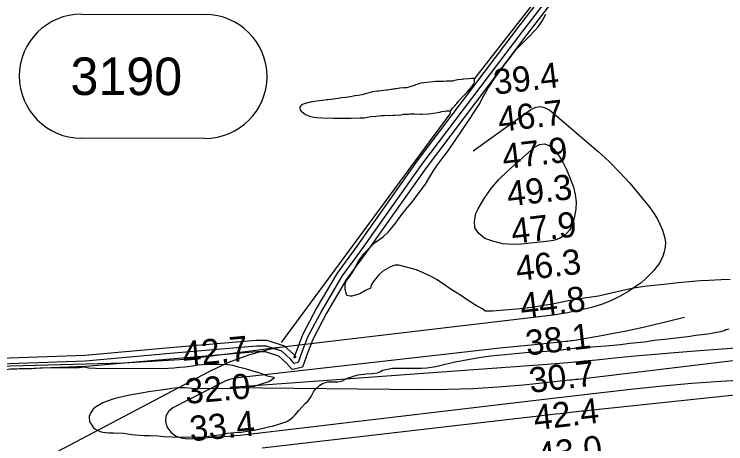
# Model space of a CAD drawing. Extents: x 3192986 to 3230865, y 867483 to 892886.
# Drawn here: x 3199829 to 3201724, y 880658 to 881802 of the extents above; entities that cross this region are included whole.
import ezdxf

# ---------------------------------------------------------------- set-up
doc = ezdxf.new("R2010")
doc.units = 0
for name, color, linetype in [('V-RIVR-RANG', 7, 'Continuous'), ('V-ROAD-CNTR', 7, 'Continuous'), ('V-ROAD-IDEN', 7, 'Continuous'), ('V-SITE-VEGE', 7, 'Continuous'), ('V-TOPO-MAJR', 7, 'Continuous'), ('V-TOPO-MINR', 7, 'Continuous'), ('V-TOPO-SHOR', 7, 'Continuous')]:
    doc.layers.add(name, color=color, linetype=linetype)

msp = doc.modelspace()

# ---------------------------------------------------------------- linework, layer by layer
at = {"layer": 'V-ROAD-CNTR'}
for points in [[(3201448.8, 882103.3), (3201182.4, 881757.5), (3200913.6, 881402.3), (3200753.9, 881176.2), (3200701.4, 881104.7), (3200647.8, 881013.7), (3200610.1, 880942), (3200596, 880905.2), (3200584.9, 880875), (3200574.7, 880872.6), (3200564.6, 880883.9), (3200541.1, 880905.2), (3200500, 880918.5), (3200474.1, 880918.4), (3200244, 880899.1), (3200018.3, 880878.8), (3199764.7, 880869.4)], [(3201402.2, 882067.4), (3201170.5, 881766.6), (3200901.5, 881411.1), (3200741.7, 881184.9), (3200688.8, 881113), (3200634.7, 881021), (3200596.4, 880948.2), (3200582, 880910.5), (3200573.6, 880887.7), (3200579.9, 880889.2), (3200575.3, 880894.5), (3200572.6, 880896.9)], [(3201427.8, 882051.6), (3201194.4, 881748.4), (3200925.7, 881393.4), (3200766, 881167.4), (3200713.9, 881096.5), (3200660.9, 881006.4), (3200623.8, 880935.8), (3200610.1, 880900), (3200596.3, 880862.2), (3200577.8, 880857.9)], [(3200572.6, 880896.9), (3200548.8, 880918.5), (3200502.3, 880933.5), (3200473.4, 880933.4), (3200242.7, 880914), (3200017.4, 880893.8), (3199764.3, 880884.3), (3199588.6, 880880.7), (3199430.3, 880873.1), (3199300.5, 880864.7), (3199227.2, 880871.2), (3199143.4, 880885.6), (3199093.7, 880891.8), (3199041.7, 880895.9), (3199014.5, 880901.6), (3199011.6, 880904.6)], [(3200577.8, 880857.9), (3200569.4, 880855.9), (3200553.9, 880873.3), (3200533.5, 880891.9), (3200497.7, 880903.5), (3200474.7, 880903.4), (3200245.3, 880884.1), (3200019.3, 880863.9), (3199765.2, 880854.4), (3199589.6, 880850.7), (3199432, 880843.2), (3199300.1, 880834.6), (3199223.3, 880841.4), (3199139, 880856), (3199090.7, 880861.9), (3199037.4, 880866.1), (3199003.9, 880873.2)]]:
    msp.add_lwpolyline(points, dxfattribs=at)
at = {"layer": 'V-ROAD-IDEN'}
for p, q in [((3200007.4, 881802.3), (3200337.4, 881801.7)), ((3200007.4, 881802.3), (3200007.4, 881802.3)), ((3200007.4, 881802.3), (3200337.4, 881801.7)), ((3200336.7, 881471.7), (3200006.7, 881472.3)), ((3200336.7, 881471.7), (3200006.7, 881472.3))]:
    msp.add_line(p, q, dxfattribs=at)
for centre, start, end in [((3200007, 881637.3), 89.8917, 269.8917), ((3200007, 881637.3), 89.8917, 269.8917), ((3200337, 881636.7), 269.8917, 89.8917), ((3200337, 881636.7), 269.8917, 89.8917)]:
    msp.add_arc(centre, 165, start, end, dxfattribs=at)
at = {"layer": 'V-SITE-VEGE'}
for p, q in [((3201235.5, 881785.4), (3201245, 881802.3)), ((3201225.1, 881769.4), (3201235.5, 881785.4)), ((3201202.4, 881745), (3201225.1, 881769.4)), ((3201166.4, 881709.4), (3201202.4, 881745)), ((3201157, 881697.1), (3201166.4, 881709.4)), ((3201144.7, 881680.2), (3201157, 881697.1)), ((3201118.1, 881644.5), (3201134.2, 881667.1)), ((3201134.2, 881667.1), (3201144.7, 881680.2)), ((3201096.4, 881613.5), (3201107.7, 881631.4)), ((3201107.7, 881631.4), (3201118.1, 881644.5)), ((3201089.7, 881604.1), (3201096.4, 881613.5)), ((3201076.4, 881579.7), (3201085.9, 881595.7)), ((3201085.9, 881595.7), (3201089.7, 881604.1)), ((3201068.8, 881564.6), (3201076.4, 881579.7)), ((3201050.8, 881538.3), (3201068.8, 881564.6)), ((3201046.1, 881528.9), (3201050.8, 881538.3)), ((3201021.5, 881493.2), (3201046.1, 881528.9)), ((3201005.4, 881468.8), (3201021.5, 881493.2)), ((3200984.5, 881438.7), (3201005.4, 881468.8)), ((3200972.2, 881422.7), (3200984.5, 881438.7)), ((3200956.1, 881401.1), (3200972.2, 881422.7)), ((3200946.6, 881387), (3200956.1, 881401.1)), ((3200933.4, 881364.5), (3200946.6, 881387)), ((3200923.9, 881349.4), (3200933.4, 881364.5)), ((3200904.9, 881324.1), (3200923.9, 881349.4)), ((3200890.7, 881304.3), (3200904.9, 881324.1)), ((3200866.1, 881276.2), (3200890.7, 881304.3)), ((3200853.8, 881259.3), (3200866.1, 881276.2)), ((3200842.4, 881243.3), (3200853.8, 881259.3)), ((3200824.5, 881221.7), (3200842.4, 881243.3)), ((3200811.2, 881209.5), (3200824.5, 881221.7)), ((3200781.9, 881187), (3200791.4, 881195.4)), ((3200791.4, 881195.4), (3200811.2, 881209.5)), ((3200762.1, 881166.3), (3200768.7, 881173.8)), ((3200768.7, 881173.8), (3200781.9, 881187)), ((3200746, 881144.7), (3200752.6, 881154.1)), ((3200752.6, 881154.1), (3200762.1, 881166.3)), ((3200730.8, 881116.5), (3200746, 881144.7)), ((3200720.4, 881100.5), (3200730.8, 881116.5)), ((3200810.9, 881118.1), (3200798.6, 881107.8)), ((3200828.8, 881128.4), (3200810.9, 881118.1)), ((3200835.4, 881131.2), (3200828.8, 881128.4)), ((3200843, 881134), (3200835.4, 881131.2)), ((3200853.3, 881133.9), (3200843, 881134)), ((3200875.9, 881128.2), (3200853.3, 881133.9)), ((3200900.4, 881121.5), (3200875.9, 881128.2)), ((3200936.1, 881105.4), (3200900.4, 881121.5)), ((3200712.8, 881092.1), (3200720.4, 881100.5)), ((3200798.6, 881107.8), (3200784.4, 881089.9)), ((3200954.9, 881094.9), (3200936.1, 881105.4)), ((3200709.9, 881082.7), (3200712.8, 881092.1)), ((3200709.9, 881071.4), (3200709.9, 881082.7)), ((3200780.6, 881082.4), (3200778.7, 881076.8)), ((3200784.4, 881089.9), (3200780.6, 881082.4)), ((3200977.5, 881079.8), (3200954.9, 881094.9)), ((3200992.5, 881069.3), (3200977.5, 881079.8)), ((3201514.5, 881077.7), (3201502.3, 881076.8)), ((3201533.4, 881079.5), (3201514.5, 881077.7)), ((3201567.3, 881083.2), (3201533.4, 881079.5)), ((3201597.5, 881086.8), (3201567.3, 881083.2)), ((3201636.1, 881090.4), (3201597.5, 881086.8)), ((3201656.8, 881092.3), (3201636.1, 881090.4)), ((3201679.5, 881093.1), (3201656.8, 881092.3)), ((3201711.5, 881094.9), (3201679.5, 881093.1)), ((3201736, 881095.7), (3201711.5, 881094.9)), ((3200712.7, 881058.2), (3200709.9, 881071.4)), ((3200764.5, 881066.4), (3200749.4, 881058)), ((3200777.7, 881073), (3200764.5, 881066.4)), ((3200778.7, 881076.8), (3200777.7, 881073)), ((3201019.8, 881052.3), (3200992.5, 881069.3)), ((3201458, 881068.5), (3201385.3, 881051.8)), ((3201478.7, 881073.1), (3201458, 881068.5)), ((3201502.3, 881076.8), (3201478.7, 881073.1)), ((3200714.5, 881053.4), (3200712.7, 881058.2)), ((3200723.9, 881051.5), (3200714.5, 881053.4)), ((3200727.7, 881051.5), (3200723.9, 881051.5)), ((3200749.4, 881058), (3200727.7, 881051.5)), ((3201037.6, 881040), (3201019.8, 881052.3)), ((3201062.1, 881024.8), (3201037.6, 881040)), ((3201335.4, 881044.5), (3201305.2, 881038.9)), ((3201385.3, 881051.8), (3201335.4, 881044.5)), ((3201076.2, 881018.1), (3201062.1, 881024.8)), ((3201234.5, 881026), (3201194, 881019.6)), ((3201262.8, 881030.6), (3201234.5, 881026)), ((3201305.2, 881038.9), (3201262.8, 881030.6)), ((3201082.8, 881011.5), (3201076.2, 881018.1)), ((3201102.5, 881011.5), (3201082.8, 881011.5)), ((3201166.6, 881016.9), (3201102.5, 881011.5)), ((3201194, 881019.6), (3201166.6, 881016.9)), ((3201724.2, 880962.9), (3201733.6, 880964.8)), ((3201623.3, 880944.5), (3201644, 880947.2)), ((3201644, 880947.2), (3201676.1, 880950.9)), ((3201676.1, 880950.9), (3201694.9, 880954.5)), ((3201694.9, 880954.5), (3201711, 880957.3)), ((3201711, 880957.3), (3201719.5, 880960.1)), ((3201719.5, 880960.1), (3201724.2, 880962.9)), ((3201443.3, 880922.5), (3201468.7, 880926.2)), ((3201468.7, 880926.2), (3201507.4, 880929.8)), ((3201507.4, 880929.8), (3201533.8, 880934.4)), ((3201533.8, 880934.4), (3201569.6, 880938.1)), ((3201569.6, 880938.1), (3201591.3, 880940.8)), ((3201591.3, 880940.8), (3201623.3, 880944.5)), ((3201246.3, 880905.4), (3201280.2, 880908.1)), ((3201280.2, 880908.1), (3201311.3, 880911.7)), ((3201311.3, 880911.7), (3201337.7, 880914.5)), ((3201337.7, 880914.5), (3201379.2, 880917.1)), ((3201379.2, 880917.1), (3201404.6, 880918.9)), ((3201404.6, 880918.9), (3201443.3, 880922.5)), ((3201022.9, 880879.9), (3201066.3, 880888.2)), ((3201066.3, 880888.2), (3201098.3, 880892.8)), ((3201098.3, 880892.8), (3201191.6, 880901.8)), ((3201191.6, 880901.8), (3201246.3, 880905.4)), ((3200318.1, 880868.4), (3200340.7, 880870.2)), ((3200340.7, 880870.2), (3200374.6, 880870.1)), ((3200374.6, 880870.1), (3200397.3, 880869.1)), ((3200397.3, 880869.1), (3200411.4, 880868.1)), ((3200952.2, 880864.1), (3200972.9, 880869.7)), ((3200972.9, 880869.7), (3201003.1, 880876.2)), ((3201003.1, 880876.2), (3201022.9, 880879.9)), ((3199817.8, 880858.1), (3199842.3, 880858.9)), ((3199842.3, 880858.9), (3199874.3, 880858.8)), ((3199874.3, 880858.8), (3199897.9, 880860.6)), ((3199897.9, 880860.6), (3199935.6, 880861.4)), ((3199935.6, 880861.4), (3200001.5, 880861.1)), ((3200001.5, 880861.1), (3200015.7, 880863)), ((3200015.7, 880863), (3200026, 880861)), ((3200026, 880861), (3200044.9, 880860)), ((3200044.9, 880860), (3200224.8, 880859.3)), ((3200224.8, 880859.3), (3200254, 880860.2)), ((3200254, 880860.2), (3200268.2, 880862)), ((3200268.2, 880862), (3200283.2, 880862.9)), ((3200283.2, 880862.9), (3200304, 880865.6)), ((3200304, 880865.6), (3200318.1, 880868.4)), ((3200411.4, 880868.1), (3200425.5, 880863.3)), ((3200425.5, 880863.3), (3200440.6, 880859.5)), ((3200440.6, 880859.5), (3200466.9, 880851.8)), ((3200466.9, 880851.8), (3200482.9, 880847.1)), ((3200800.4, 880848.7), (3200806.1, 880851.5)), ((3200806.1, 880851.5), (3200809.9, 880854.3)), ((3200809.9, 880854.3), (3200836.3, 880859.8)), ((3200836.3, 880859.8), (3200913.5, 880859.5)), ((3200913.5, 880859.5), (3200927.7, 880860.4)), ((3200927.7, 880860.4), (3200952.2, 880864.1)), ((3200482.9, 880847.1), (3200496.1, 880842.3)), ((3200496.1, 880842.3), (3200502.7, 880839.4)), ((3200502.7, 880839.4), (3200511.1, 880837.5)), ((3200521.5, 880832.8), (3200508.3, 880824.3)), ((3200511.1, 880837.5), (3200520.6, 880835.6)), ((3200520.6, 880835.6), (3200521.5, 880832.8)), ((3200703.3, 880826.4), (3200715.6, 880833)), ((3200715.6, 880833), (3200725, 880835.8)), ((3200725, 880835.8), (3200735.4, 880839.5)), ((3200735.4, 880839.5), (3200744.8, 880842.3)), ((3200744.8, 880842.3), (3200766.5, 880845)), ((3200766.5, 880845), (3200781.6, 880845.9)), ((3200781.6, 880845.9), (3200796.6, 880847.7)), ((3200796.6, 880847.7), (3200800.4, 880848.7)), ((3200486.6, 880816.9), (3200466.8, 880811.3)), ((3200508.3, 880824.3), (3200486.6, 880816.9)), ((3200631.6, 880804.1), (3200643, 880814.4)), ((3200643, 880814.4), (3200651.5, 880820)), ((3200651.5, 880820), (3200663.7, 880823.8)), ((3200663.7, 880823.8), (3200691, 880823.6)), ((3200691, 880823.6), (3200703.3, 880826.4)), ((3200168, 880793.6), (3200140.7, 880789)), ((3200185.9, 880796.4), (3200168, 880793.6)), ((3200213.3, 880800), (3200185.9, 880796.4)), ((3200231.2, 880802.8), (3200213.3, 880800)), ((3200248.2, 880805.6), (3200231.2, 880802.8)), ((3200263.2, 880807.4), (3200248.2, 880805.6)), ((3200283, 880807.3), (3200263.2, 880807.4)), ((3200301.9, 880805.3), (3200283, 880807.3)), ((3200413, 880804.9), (3200301.9, 880805.3)), ((3200433.8, 880807.7), (3200413, 880804.9)), ((3200456.4, 880810.4), (3200433.8, 880807.7)), ((3200466.8, 880811.3), (3200456.4, 880810.4)), ((3200619.3, 880784.4), (3200625.9, 880796.6)), ((3200625.9, 880796.6), (3200631.6, 880804.1)), ((3200093.5, 880777.9), (3200078.4, 880773.2)), ((3200119.9, 880784.4), (3200093.5, 880777.9)), ((3200140.7, 880789), (3200119.9, 880784.4)), ((3200609.8, 880771.2), (3200616.4, 880778.7)), ((3200616.4, 880778.7), (3200619.3, 880784.4)), ((3200045.4, 880755.5), (3200038.8, 880750.8)), ((3200055.8, 880762), (3200045.4, 880755.5)), ((3200064.3, 880767.6), (3200055.8, 880762)), ((3200078.4, 880773.2), (3200064.3, 880767.6)), ((3200587.1, 880746.8), (3200603.2, 880764.6)), ((3200603.2, 880764.6), (3200609.8, 880771.2)), ((3200032.1, 880739.5), (3200028.3, 880731)), ((3200038.8, 880750.8), (3200032.1, 880739.5)), ((3200576.7, 880735.5), (3200587.1, 880746.8)), ((3200028.3, 880731), (3200029.2, 880716.9)), ((3200528.5, 880708.4), (3200555, 880717.7)), ((3200555, 880717.7), (3200564.4, 880724.3)), ((3200564.4, 880724.3), (3200572, 880729.9)), ((3200572, 880729.9), (3200576.7, 880735.5)), ((3200029.2, 880716.9), (3200032, 880713.1)), ((3200032, 880713.1), (3200039.5, 880700.8)), ((3200039.5, 880700.8), (3200045.2, 880697)), ((3200468.2, 880694.5), (3200488, 880699.1)), ((3200488, 880699.1), (3200509.7, 880704.7)), ((3200509.7, 880704.7), (3200516.3, 880705.6)), ((3200516.3, 880705.6), (3200528.5, 880708.4)), ((3200045.2, 880697), (3200057.4, 880691.3)), ((3200057.4, 880691.3), (3200064.9, 880689.4)), ((3200064.9, 880689.4), (3200080.9, 880687.5)), ((3200080.9, 880687.5), (3200093.2, 880687.4)), ((3200093.2, 880687.4), (3200119.6, 880686.4)), ((3200119.6, 880686.4), (3200141.2, 880683.5)), ((3200141.2, 880683.5), (3200174.2, 880680.5)), ((3200174.2, 880680.5), (3200189.3, 880680.5)), ((3200189.3, 880680.5), (3200211.9, 880679.4)), ((3200211.9, 880679.4), (3200226, 880677.5)), ((3200332.5, 880677.1), (3200354.1, 880679.8)), ((3200354.1, 880679.8), (3200381.5, 880683.5)), ((3200381.5, 880683.5), (3200396.6, 880686.3)), ((3200396.6, 880686.3), (3200416.3, 880688.1)), ((3200416.3, 880688.1), (3200432.4, 880689)), ((3200432.4, 880689), (3200468.2, 880694.5)), ((3200226, 880677.5), (3200248.6, 880676.5)), ((3200248.6, 880676.5), (3200310.8, 880676.2)), ((3200310.8, 880676.2), (3200332.5, 880677.1))]:
    msp.add_line(p, q, dxfattribs=at)
at = {"layer": 'V-TOPO-MAJR'}
msp.add_lwpolyline([(3201613.9, 880994.4), (3201533.9, 880975.1), (3201496.4, 880966.5), (3201458.8, 880958.4), (3201421, 880951.1), (3201383.2, 880944.3), (3201315.7, 880932.9), (3201311.5, 880932.3), (3201307.3, 880931.7), (3201303, 880931.2), (3201298.8, 880930.7), (3201214.6, 880922.3), (3201168.2, 880917.6), (3201121.9, 880912.8), (3201075.6, 880907.8), (3201029.3, 880902.6), (3200425.5, 880834.4), (3200414.1, 880832.5), (3200402.9, 880829.7), (3200392, 880825.8), (3200381.4, 880821.1), (3200251.1, 880754.4), (3200239.6, 880744), (3200232.4, 880732.3), (3200231.5, 880718.5), (3200234.9, 880703.3), (3200245.5, 880689.7), (3200258.1, 880679.4), (3200273.4, 880674), (3200290.5, 880671.9), (3200387.1, 880677.9), (3200401.7, 880679), (3200416.2, 880680.1), (3200430.8, 880681.6), (3200445.3, 880683.1), (3200595.9, 880700.7), (3200685.7, 880711.2), (3200775.6, 880721.8), (3200865.4, 880732.4), (3200955.2, 880743.1), (3201278.9, 880781.6), (3201301.7, 880784.3), (3201324.5, 880787), (3201347.4, 880789.6), (3201370.2, 880792.3), (3201478.9, 880805), (3201556.2, 880813.1), (3201633.6, 880820.1), (3201711.1, 880825.4), (3201788.6, 880829.6)], dxfattribs=at)
at = {"layer": 'V-TOPO-MINR'}
for points in [[(3201051.3, 881438.2), (3201205.2, 881548.9), (3201218.1, 881554.5), (3201230.8, 881556.6), (3201243.3, 881553.4), (3201255.7, 881546.7), (3201383.8, 881436.6), (3201413.2, 881409.8), (3201441.5, 881382), (3201468.2, 881352.6), (3201493.9, 881322.2), (3201521.8, 881287.2), (3201531.9, 881273.1), (3201541, 881258.5), (3201548.7, 881243.1), (3201555.3, 881227.1), (3201558.5, 881218.2), (3201561.6, 881206.2), (3201563.2, 881194.2), (3201562.5, 881182), (3201560.4, 881169.8), (3201556.3, 881158), (3201551.3, 881146.6), (3201544.8, 881136), (3201537.4, 881125.9), (3201533, 881120.6), (3201522.2, 881108.8), (3201510.7, 881097.6), (3201498.4, 881087.4), (3201485.5, 881077.9), (3201466.2, 881065.1), (3201442.6, 881051.1), (3201418.3, 881038.8), (3201392.7, 881029.2), (3201366.4, 881021.4), (3201332, 881013.1), (3201315.2, 881009.4), (3201298.3, 881006.1), (3201281.4, 881003.4), (3201264.3, 881001.1), (3200565.5, 880918.7), (3200537, 880914.5), (3200508.7, 880909.3), (3200480.8, 880902.4), (3200453.1, 880894.5), (3200425.9, 880885), (3200399.1, 880874.6), (3200372.9, 880862.8), (3200347, 880850.1), (3199925.8, 880628.1)], [(3201241.1, 881457.6), (3201253.6, 881453.1), (3201265.8, 881444.2), (3201268.3, 881441.1), (3201280.2, 881424.3), (3201291.1, 881406.8), (3201300.2, 881388.4), (3201308.1, 881369.4), (3201318.2, 881341.5), (3201323.2, 881322.3), (3201325.8, 881303), (3201324.9, 881283.5), (3201321.6, 881263.9), (3201316.7, 881245.7), (3201312.9, 881235.9), (3201307.9, 881226.9), (3201301.1, 881219.2), (3201293.2, 881212.3), (3201283.9, 881207), (3201274.3, 881202.6), (3201264.1, 881199.7), (3201253.6, 881197.7), (3201180, 881189.9), (3201154.9, 881189.2), (3201130.1, 881191.2), (3201106, 881196.9), (3201082.2, 881205.3), (3201066.3, 881218.4), (3201056.1, 881233.5), (3201054.5, 881251.6), (3201058.6, 881271.8), (3201064.8, 881283.9), (3201080.9, 881311.6), (3201098.9, 881337.9), (3201119.8, 881362), (3201142.6, 881384.7), (3201214.5, 881448.7), (3201228, 881455.4), (3201241.1, 881457.6)], [(3201954.3, 880927.7), (3201630.8, 880904.1), (3201577.9, 880900), (3201525.1, 880895.6), (3201472.3, 880890.7), (3201419.5, 880885.5), (3201379.5, 880881.4), (3201346.8, 880878.1), (3201314, 880875.1), (3201281.2, 880872.4), (3201248.4, 880869.8), (3200406.3, 880808.7), (3200406, 880808.6), (3200405.3, 880808.6), (3200404.4, 880808.5), (3200404.3, 880808.4), (3200404.2, 880808.3), (3200404.2, 880808.2), (3200404.5, 880808), (3200404.7, 880808), (3200915.5, 880803), (3200983, 880803.5), (3201050.4, 880805.5), (3201117.8, 880809.8), (3201185, 880815.6), (3201308.2, 880828.3), (3201313.8, 880828.9), (3201319.5, 880829.5), (3201325.1, 880830.1), (3201330.7, 880830.8), (3201905.5, 880899.5)], [(3200489.3, 880647.4), (3201271.9, 880737.8), (3201281.5, 880738.9), (3201291.1, 880740), (3201300.8, 880741.1), (3201310.4, 880742.3), (3201326.5, 880744.2), (3201328, 880744.3), (3201332.8, 880744.9), (3201340.1, 880745.7), (3201345.3, 880746.3), (3201350.5, 880746.9), (3201355.7, 880747.4), (3201361, 880748), (3201782.1, 880792.5)]]:
    msp.add_lwpolyline(points, dxfattribs=at)
at = {"layer": 'V-TOPO-SHOR'}
msp.add_line((3201360.7, 882023), (3201055.1, 881631), dxfattribs=at)
for points in [[(3201055.1, 881631), (3201046.6, 881630.9), (3201040.4, 881630.1), (3201024.9, 881629), (3201021.5, 881628.4), (3201010.7, 881627.2), (3201001.1, 881625.7), (3200996, 881624.5), (3200992.6, 881624.3), (3200988.2, 881623.7), (3200981.2, 881623.7), (3200972.5, 881623.4), (3200957.1, 881623.2), (3200951.6, 881622.9), (3200944.8, 881622.7), (3200911.5, 881618.6), (3200904.2, 881616.5), (3200897.6, 881614.3), (3200893.8, 881612.7), (3200879.4, 881608.4), (3200873.5, 881606.4), (3200865.9, 881606.5), (3200855.5, 881605.1), (3200847.4, 881603.7), (3200844.2, 881603.4), (3200840.8, 881603.2), (3200836.8, 881602.6), (3200822.7, 881600.1), (3200819.1, 881599.9), (3200800, 881597.6), (3200796.2, 881597.6), (3200783.4, 881595.6), (3200776.4, 881593.9), (3200754.3, 881587.8), (3200745, 881586), (3200736.4, 881584.9), (3200724.8, 881582.7), (3200717.1, 881581.5), (3200710.7, 881581), (3200700.1, 881579.6), (3200691.8, 881578.3), (3200685.2, 881576.9), (3200665.1, 881574.4), (3200661.1, 881574.2), (3200655.7, 881573.2), (3200634.8, 881570.7), (3200624.4, 881569.2), (3200620.9, 881568.8), (3200615.5, 881567.6), (3200609.9, 881566.6), (3200600.7, 881563.7), (3200596.9, 881562.1), (3200594.3, 881560.5), (3200591.5, 881557.7), (3200589.3, 881554.6), (3200589.1, 881551), (3200590.1, 881547.8), (3200592.9, 881544.6), (3200599.8, 881538.6), (3200604.8, 881535.6), (3200609.2, 881533.4), (3200615.1, 881531), (3200622.3, 881529.1), (3200626.9, 881528.3), (3200634.2, 881527.5), (3200649.6, 881526.3), (3200679.2, 881525.3), (3200692.8, 881525.3), (3200709.7, 881525.8), (3200723, 881525.8), (3200726.4, 881525.6), (3200749.1, 881526.3), (3200752.5, 881526.1), (3200756.5, 881526.2), (3200760.7, 881526.8), (3200770, 881528.6), (3200779, 881529.9), (3200791.7, 881530.9), (3200801.9, 881532), (3200807.1, 881532.2), (3200812.1, 881532.6), (3200815.4, 881532.6), (3200823.4, 881533.2), (3200827.6, 881532.9), (3200837.9, 881533.5), (3200842.1, 881533.5), (3200858.4, 881534.8), (3200865.4, 881535.8), (3200872.8, 881536.4), (3200880.2, 881536.3), (3200883.5, 881536.7), (3200894.9, 881536.9), (3200910.2, 881536), (3200913.8, 881536), (3200930.9, 881536.7), (3200939.1, 881537.7), (3200962, 881541.4), (3200968, 881543), (3200974.6, 881544.3), (3200979.3, 881544.9), (3200982.5, 881545.1)], [(3200982.5, 881545.1), (3200985.9, 881545.1), (3200989.1, 881544.9), (3200992.1, 881546.1), (3200994.1, 881549.2), (3200996.5, 881552.4), (3201002.9, 881559.5), (3201005.1, 881562.3), (3201007.3, 881564.7), (3201012.3, 881570.7), (3201015.7, 881574.2), (3201023.5, 881583), (3201032.7, 881591.9), (3201035.1, 881594.5), (3201040.9, 881601), (3201046.1, 881607.6), (3201051.1, 881614.7), (3201052.9, 881617.5), (3201054.9, 881621.1), (3201055.1, 881631)], [(3200540.7, 880928.5), (3200747.3, 881208.5), (3200989.6, 881537.5), (3200992.1, 881546.1)], [(3200534.2, 880915), (3200285.3, 880882.4), (3200119.5, 880872.9), (3199682.9, 880861.2), (3199446.9, 880849.2), (3199329, 880845.6), (3199178.9, 880815.2), (3199064.1, 880800.4), (3198995.5, 880794.7), (3198740.4, 880778), (3198145.9, 880755.2), (3197602.5, 880742.9), (3197204.9, 880739.5)]]:
    msp.add_lwpolyline(points, dxfattribs=at)

# ---------------------------------------------------------------- texts
at = {"layer": 'V-RIVR-RANG'}
for s, rotation, p in [('39.4', 6.6683, (3201109.3, 881588)), ('46.7', 6.6683, (3201121.1, 881488.7)), ('47.9', 6.6683, (3201132.7, 881389.4)), ('49.3', 6.6683, (3201144.8, 881290.1)), ('47.9', 6.6683, (3201156.4, 881190.8)), ('46.3', 6.6683, (3201168.5, 881091.5)), ('44.8', 6.6683, (3201180.4, 880992.2)), ('38.1', 6.6683, (3201194.6, 880893.2)), ('42.7', 5.1183, (3200280, 880864.1)), ('30.7', 6.6683, (3201204.1, 880793.6)), ('32.0', 5.1183, (3200286.3, 880764.2)), ('42.4', 6.6683, (3201216, 880694.3)), ('33.4', 5.1183, (3200298.3, 880664.9)), ('43.0', 6.6683, (3201225, 880594.7))]:
    msp.add_text(s, height=67, rotation=rotation, dxfattribs=at).set_placement(p)
at = {"layer": 'V-ROAD-IDEN'}
msp.add_text(' 3190', height=100, rotation=359.8918, dxfattribs=at).set_placement((3199941.2, 881587.4))

doc.saveas('drawing.dxf')
